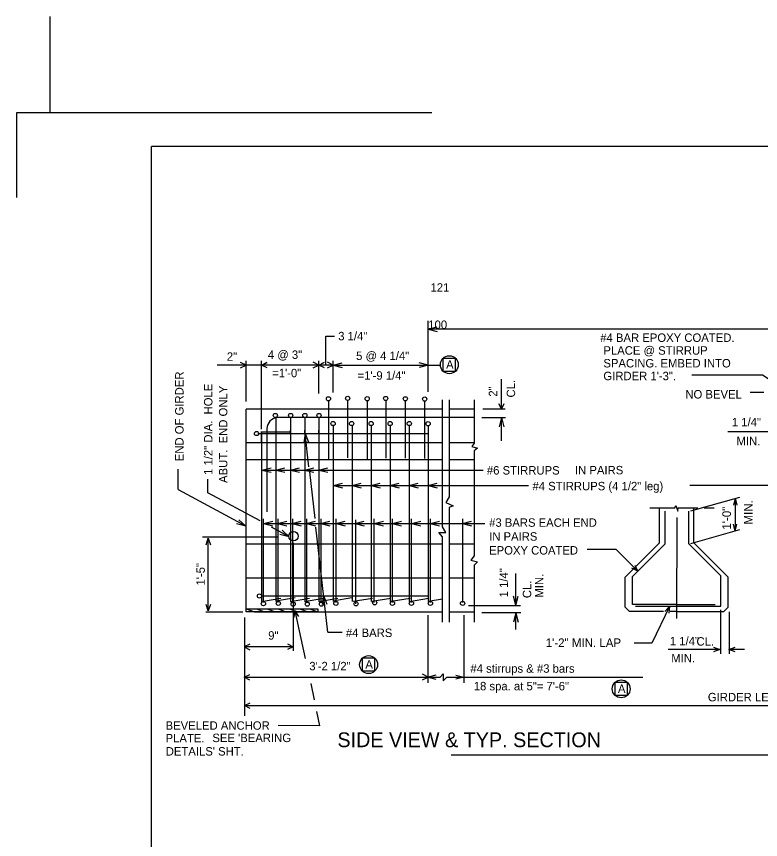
# Model space of a CAD drawing. Extents: x 1005.3 to 1101.9, y 1996.5 to 2073.3.
# Drawn here: x 1008.52 to 1037.89, y 2040.81 to 2073.29 of the extents above; entities that cross this region are included whole.
import ezdxf

# ---------------------------------------------------------------- set-up
doc = ezdxf.new("R2010")
doc.units = 0
for name, color, linetype in [('Level 1', 7, 'Continuous'), ('Level 2', 7, 'Continuous'), ('Level 5', 7, 'Continuous'), ('Level 6', 7, 'Continuous'), ('Level 60', 7, 'Continuous')]:
    doc.layers.add(name, color=color, linetype=linetype)

msp = doc.modelspace()

# ---------------------------------------------------------------- linework, layer by layer
at = {"layer": 'Level 1'}
for p, q in [((1024.919, 2069.489), (1008.518, 2069.489)), ((1008.518, 2069.489), (1008.518, 2066.149)), ((1013.852, 2012.158), (1013.852, 2068.156)), ((1097.517, 2068.156), (1013.852, 2068.156))]:
    msp.add_line(p, q, dxfattribs=at)
at = {"layer": 'Level 2'}
for p, q in [((1009.852, 2069.489), (1009.852, 2073.293)), ((1024.77, 2060.812), (1024.77, 2061.278)), ((1024.765, 2060.951), (1025.125, 2061.041)), ((1024.765, 2060.951), (1025.125, 2060.861)), ((1024.771, 2058.471), (1024.771, 2060.959)), ((1024.772, 2060.959), (1050.923, 2060.959)), ((1020.725, 2059.534), (1020.725, 2060.679)), ((1020.725, 2060.679), (1021.066, 2060.679)), ((1017.583, 2058.096), (1017.583, 2059.701)), ((1018.196, 2057.002), (1018.196, 2059.701)), ((1020.452, 2058.408), (1020.452, 2059.701)), ((1021.021, 2058.45), (1021.021, 2059.701)), ((1025.855, 2059.797), (1025.355, 2059.797)), ((1025.355, 2059.797), (1025.355, 2059.297)), ((1025.855, 2059.297), (1025.855, 2059.797)), ((1018.196, 2059.528), (1016.436, 2059.528)), ((1021.021, 2059.534), (1018.196, 2059.534)), ((1021.021, 2059.534), (1021.381, 2059.624)), ((1021.021, 2059.534), (1025.246, 2059.534)), ((1021.021, 2059.534), (1021.381, 2059.444)), ((1024.771, 2059.534), (1024.411, 2059.624)), ((1024.771, 2059.534), (1024.411, 2059.624)), ((1024.771, 2059.534), (1024.411, 2059.444)), ((1024.771, 2059.534), (1024.411, 2059.444)), ((1025.355, 2059.297), (1025.855, 2059.297)), ((1025.36, 2059.297), (1025.36, 2059.297)), ((1027.661, 2057.795), (1027.661, 2058.977)), ((1038.024, 2058.448), (1037.478, 2058.448)), ((1020.836, 2058.112), (1020.836, 2055.824)), ((1021.585, 2058.136), (1021.585, 2055.872)), ((1022.367, 2058.12), (1022.367, 2055.824)), ((1023.1, 2058.12), (1023.1, 2055.856)), ((1023.865, 2058.12), (1023.865, 2055.856)), ((1024.63, 2058.104), (1024.63, 2055.84)), ((1025.329, 2053.154), (1025.329, 2058.16)), ((1025.593, 2058.16), (1025.593, 2054.339)), ((1026.586, 2058.16), (1026.586, 2056.448)), ((1017.583, 2049.915), (1017.583, 2057.795)), ((1025.329, 2057.795), (1017.583, 2057.795)), ((1026.586, 2057.795), (1025.593, 2057.795)), ((1026.926, 2057.805), (1027.804, 2057.805)), ((1018.76, 2057.461), (1018.76, 2051.385)), ((1026.586, 2057.461), (1018.806, 2057.461)), ((1019.338, 2057.461), (1019.338, 2050.206)), ((1019.897, 2057.461), (1019.897, 2050.206)), ((1020.457, 2057.461), (1020.457, 2050.206)), ((1026.89, 2057.461), (1027.828, 2057.461)), ((1027.661, 2057.461), (1027.571, 2057.101)), ((1027.661, 2056.545), (1027.661, 2057.461)), ((1027.661, 2057.461), (1027.751, 2057.101)), ((1021.021, 2057.131), (1021.021, 2050.206)), ((1021.771, 2057.139), (1021.771, 2050.206)), ((1022.521, 2057.155), (1022.521, 2050.206)), ((1023.271, 2057.147), (1023.271, 2050.206)), ((1024.021, 2057.139), (1024.021, 2050.206)), ((1024.771, 2057.131), (1024.771, 2050.206)), ((1018.043, 2056.838), (1024.771, 2056.838)), ((1018.196, 2056.481), (1018.196, 2056.909)), ((1018.196, 2056.905), (1019.326, 2056.905)), ((1018.196, 2056.905), (1018.196, 2050.206)), ((1018.399, 2057.026), (1018.399, 2053.739)), ((1019.338, 2056.808), (1019.338, 2056.969)), ((1019.911, 2056.838), (1019.863, 2056.47)), ((1019.897, 2056.808), (1019.897, 2056.969)), ((1019.911, 2056.838), (1020.042, 2056.491)), ((1020.062, 2055.523), (1019.911, 2056.838)), ((1020.457, 2056.808), (1020.457, 2056.969)), ((1039.42, 2056.897), (1036.598, 2056.897)), ((1025.329, 2056.461), (1017.583, 2056.461)), ((1026.586, 2056.461), (1025.593, 2056.461)), ((1026.586, 2056.448), (1026.487, 2056.316)), ((1037.712, 2056.58), (1037.712, 2056.58)), ((1026.487, 2056.316), (1026.718, 2056.25)), ((1026.718, 2056.25), (1026.586, 2056.151)), ((1026.586, 2056.151), (1026.586, 2052.002)), ((1025.329, 2055.794), (1017.583, 2055.794)), ((1026.586, 2055.794), (1025.593, 2055.794)), ((1014.904, 2054.622), (1014.904, 2055.42)), ((1018.206, 2055.392), (1018.566, 2055.482)), ((1018.755, 2055.392), (1019.115, 2055.482)), ((1019.335, 2055.392), (1019.695, 2055.482)), ((1019.891, 2055.392), (1020.251, 2055.482)), ((1020.454, 2055.391), (1020.814, 2055.481)), ((1018.206, 2055.392), (1018.91, 2055.392)), ((1018.206, 2055.392), (1018.566, 2055.302)), ((1018.755, 2055.392), (1019.115, 2055.302)), ((1018.91, 2055.392), (1019.613, 2055.392)), ((1019.335, 2055.392), (1019.695, 2055.302)), ((1019.613, 2055.392), (1026.945, 2055.392)), ((1019.891, 2055.392), (1020.251, 2055.302)), ((1020.086, 2055.314), (1020.297, 2053.481)), ((1020.454, 2055.391), (1020.814, 2055.301)), ((1021.032, 2054.777), (1021.392, 2054.867)), ((1021.032, 2054.777), (1021.769, 2054.777)), ((1021.032, 2054.777), (1021.392, 2054.687)), ((1021.769, 2054.777), (1022.129, 2054.867)), ((1021.769, 2054.777), (1022.54, 2054.777)), ((1021.769, 2054.777), (1022.129, 2054.687)), ((1022.518, 2054.777), (1022.878, 2054.867)), ((1022.518, 2054.777), (1022.878, 2054.687)), ((1022.54, 2054.777), (1023.299, 2054.777)), ((1023.269, 2054.777), (1023.629, 2054.867)), ((1023.269, 2054.777), (1023.629, 2054.687)), ((1023.299, 2054.777), (1024.036, 2054.777)), ((1024.016, 2054.777), (1024.376, 2054.867)), ((1024.016, 2054.777), (1024.376, 2054.687)), ((1024.036, 2054.777), (1024.784, 2054.777)), ((1024.769, 2054.777), (1025.129, 2054.867)), ((1024.769, 2054.777), (1025.129, 2054.687)), ((1024.784, 2054.777), (1028.735, 2054.777)), ((1039.747, 2054.777), (1035.097, 2054.777)), ((1014.904, 2054.622), (1017.583, 2053.169)), ((1025.593, 2054.339), (1025.461, 2054.11)), ((1035.141, 2053.782), (1037.069, 2054.325)), ((1036.884, 2054.276), (1036.816, 2054.004)), ((1036.884, 2054.276), (1036.952, 2054.004)), ((1036.887, 2054.284), (1036.887, 2053)), ((1025.461, 2054.11), (1025.757, 2053.978)), ((1025.757, 2053.978), (1025.593, 2053.912)), ((1025.593, 2053.912), (1025.593, 2049.39)), ((1033.515, 2053.902), (1034.5, 2053.902)), ((1033.9, 2052.521), (1033.9, 2053.902)), ((1034.5, 2053.902), (1034.552, 2053.991)), ((1034.552, 2053.991), (1034.629, 2053.764)), ((1034.629, 2053.764), (1034.639, 2053.902)), ((1034.639, 2053.902), (1035.416, 2053.902)), ((1035.257, 2052.521), (1035.257, 2053.902)), ((1035.664, 2053.902), (1036.053, 2053.902)), ((1018.251, 2053.471), (1018.251, 2050.165)), ((1018.839, 2053.471), (1018.839, 2050.165)), ((1019.412, 2053.471), (1019.412, 2050.165)), ((1019.971, 2053.471), (1019.971, 2050.165)), ((1020.531, 2053.471), (1020.531, 2050.165)), ((1021.121, 2053.471), (1021.121, 2050.165)), ((1022.629, 2053.471), (1022.629, 2050.165)), ((1023.353, 2053.471), (1023.353, 2050.165)), ((1024.103, 2053.471), (1024.103, 2050.165)), ((1024.853, 2053.471), (1024.853, 2050.165)), ((1026.124, 2053.471), (1026.124, 2050.165)), ((1034.129, 2052.474), (1034.129, 2053.762)), ((1034.579, 2049.537), (1034.594, 2053.522)), ((1035.058, 2052.474), (1035.058, 2053.762)), ((1017.566, 2053.179), (1017.206, 2053.272)), ((1017.566, 2053.179), (1017.292, 2053.43)), ((1018.273, 2053.281), (1018.633, 2053.371)), ((1018.273, 2053.281), (1018.988, 2053.281)), ((1018.273, 2053.281), (1018.633, 2053.191)), ((1018.828, 2053.281), (1019.188, 2053.371)), ((1018.828, 2053.281), (1019.188, 2053.191)), ((1018.988, 2053.281), (1019.691, 2053.281)), ((1019.403, 2053.281), (1019.763, 2053.371)), ((1019.403, 2053.281), (1019.763, 2053.191)), ((1019.691, 2053.281), (1021.132, 2053.281)), ((1019.967, 2053.281), (1020.327, 2053.371)), ((1019.967, 2053.281), (1020.327, 2053.191)), ((1020.529, 2053.281), (1020.889, 2053.371)), ((1020.529, 2053.281), (1020.889, 2053.191)), ((1021.132, 2053.281), (1021.492, 2053.371)), ((1021.132, 2053.281), (1022.64, 2053.281)), ((1021.132, 2053.281), (1021.492, 2053.191)), ((1021.886, 2053.281), (1022.246, 2053.371)), ((1021.886, 2053.281), (1022.246, 2053.191)), ((1021.895, 2053.419), (1021.895, 2050.113)), ((1022.64, 2053.281), (1023, 2053.371)), ((1022.64, 2053.281), (1024.114, 2053.281)), ((1022.64, 2053.281), (1023, 2053.191)), ((1023.353, 2053.281), (1023.713, 2053.371)), ((1023.353, 2053.281), (1023.713, 2053.191)), ((1024.114, 2053.281), (1024.474, 2053.371)), ((1024.114, 2053.281), (1027.008, 2053.281)), ((1024.114, 2053.281), (1024.474, 2053.191)), ((1024.853, 2053.281), (1025.213, 2053.371)), ((1024.853, 2053.281), (1025.213, 2053.191)), ((1025.461, 2052.924), (1025.329, 2053.154)), ((1026.124, 2053.281), (1026.484, 2053.371)), ((1026.124, 2053.281), (1026.484, 2053.191)), ((1036.884, 2052.978), (1036.816, 2053.25)), ((1036.884, 2052.978), (1036.952, 2053.25)), ((1020.813, 2048.987), (1020.336, 2053.139)), ((1025.329, 2052.759), (1025.197, 2052.924)), ((1025.197, 2052.924), (1025.461, 2052.924)), ((1035.14, 2052.496), (1037.068, 2053.039)), ((1025.329, 2049.39), (1025.329, 2052.759)), ((1032.542, 2051.163), (1033.9, 2052.521)), ((1036.615, 2051.163), (1035.257, 2052.521)), ((1025.329, 2052.46), (1017.583, 2052.46)), ((1026.586, 2052.46), (1025.593, 2052.46)), ((1032.196, 2052.25), (1031.047, 2052.25)), ((1033.051, 2051.395), (1032.196, 2052.25)), ((1032.841, 2051.186), (1034.129, 2052.474)), ((1036.316, 2051.216), (1035.058, 2052.474)), ((1026.586, 2052.002), (1026.454, 2051.837)), ((1026.454, 2051.837), (1026.718, 2051.771)), ((1026.718, 2051.771), (1026.586, 2051.639)), ((1026.586, 2051.639), (1026.586, 2049.39)), ((1018.76, 2051.385), (1018.76, 2050.206)), ((1028.226, 2050.055), (1028.226, 2051.312)), ((1036.316, 2050.015), (1036.316, 2051.216)), ((1025.329, 2051.127), (1017.583, 2051.127)), ((1026.586, 2051.127), (1025.593, 2051.127)), ((1032.542, 2049.974), (1032.542, 2051.163)), ((1032.841, 2050.084), (1032.841, 2051.186)), ((1036.615, 2049.974), (1036.615, 2051.163)), ((1018.196, 2050.421), (1024.771, 2050.421)), ((1018.196, 2050.206), (1018.949, 2050.327)), ((1018.76, 2050.233), (1019.514, 2050.354)), ((1019.329, 2050.206), (1020.082, 2050.327)), ((1019.888, 2050.206), (1020.642, 2050.327)), ((1020.448, 2050.206), (1021.201, 2050.327)), ((1020.635, 2050.445), (1020.587, 2050.077)), ((1020.635, 2050.445), (1020.765, 2050.097)), ((1021.008, 2050.233), (1021.761, 2050.354)), ((1021.815, 2050.219), (1022.568, 2050.34)), ((1022.541, 2050.219), (1023.295, 2050.34)), ((1023.308, 2050.219), (1024.062, 2050.34)), ((1024.035, 2050.206), (1024.788, 2050.327)), ((1024.775, 2050.219), (1025.329, 2050.308)), ((1028.226, 2050.055), (1028.136, 2050.415)), ((1028.226, 2050.055), (1028.316, 2050.415)), ((1017.583, 2049.915), (1017.913, 2049.792)), ((1026.365, 2050.047), (1028.412, 2050.047)), ((1032.711, 2049.802), (1032.542, 2049.974)), ((1034.58, 2050.084), (1032.841, 2050.084)), ((1032.958, 2050.015), (1036.316, 2050.015)), ((1034.3, 2050.003), (1033.601, 2048.561)), ((1034.577, 2050.084), (1036.103, 2050.084)), ((1036.446, 2049.802), (1036.615, 2049.974)), ((1017.913, 2049.792), (1025.329, 2049.792)), ((1024.771, 2046.987), (1024.771, 2049.659)), ((1025.593, 2049.792), (1026.586, 2049.792)), ((1026.172, 2049.659), (1026.172, 2046.987)), ((1026.887, 2049.771), (1028.426, 2049.771)), ((1028.226, 2049.745), (1028.136, 2049.385)), ((1028.226, 2049.101), (1028.226, 2049.771)), ((1028.226, 2049.745), (1028.316, 2049.385)), ((1034.057, 2049.802), (1032.711, 2049.802)), ((1034.579, 2049.802), (1034.328, 2049.802)), ((1034.579, 2049.802), (1034.579, 2049.802)), ((1034.579, 2049.802), (1034.579, 2049.802)), ((1034.579, 2049.802), (1034.579, 2049.802)), ((1034.579, 2049.802), (1034.579, 2049.802)), ((1034.579, 2049.802), (1034.579, 2049.802)), ((1034.579, 2049.802), (1036.446, 2049.802)), ((1034.579, 2049.802), (1034.579, 2049.802)), ((1034.579, 2049.802), (1034.579, 2049.802)), ((1034.579, 2049.802), (1034.579, 2049.802)), ((1036.315, 2049.876), (1036.315, 2048.14)), ((1036.654, 2049.798), (1036.654, 2048.14)), ((1017.519, 2049.568), (1017.519, 2045.693)), ((1020.813, 2048.987), (1021.369, 2048.987)), ((1033.601, 2048.561), (1032.903, 2048.561)), ((1036.286, 2048.306), (1034.238, 2048.306)), ((1037.252, 2048.306), (1036.639, 2048.306)), ((1022.669, 2047.961), (1022.169, 2047.961)), ((1022.169, 2047.961), (1022.169, 2047.461)), ((1022.669, 2047.461), (1022.669, 2047.961)), ((1022.169, 2047.461), (1022.669, 2047.461)), ((1022.173, 2047.461), (1022.173, 2047.461)), ((1025.239, 2047.221), (1025.363, 2047.344)), ((1025.363, 2047.344), (1025.363, 2047.073)), ((1017.527, 2047.221), (1024.764, 2047.221)), ((1024.764, 2047.221), (1025.239, 2047.221)), ((1025.363, 2047.073), (1025.511, 2047.221)), ((1025.511, 2047.221), (1033.243, 2047.221)), ((1032.639, 2047.004), (1032.139, 2047.004)), ((1032.139, 2047.004), (1032.139, 2046.504)), ((1032.639, 2046.504), (1032.639, 2047.004)), ((1032.139, 2046.504), (1032.639, 2046.504)), ((1032.144, 2046.504), (1032.144, 2046.504)), ((1017.519, 2046.095), (1056.542, 2046.095)), ((1025.674, 2044.148), (1042.378, 2044.148))]:
    msp.add_line(p, q, dxfattribs=at)
for points in [[(1017.361, 2059.419), (1017.583, 2059.53), (1017.361, 2059.641)], [(1018.418, 2059.423), (1018.196, 2059.534), (1018.418, 2059.645)], [(1018.418, 2059.419), (1018.196, 2059.53), (1018.418, 2059.641)], [(1020.23, 2059.423), (1020.452, 2059.534), (1020.23, 2059.645)], [(1020.675, 2059.423), (1020.452, 2059.534), (1020.675, 2059.645)], [(1020.799, 2059.423), (1021.021, 2059.534), (1020.799, 2059.645)], [(1024.766, 2059.531), (1024.771, 2059.534), (1024.766, 2059.537)], [(1039.799, 2057.948), (1037.964, 2059.132), (1035.18, 2059.132)], [(1027.55, 2058.017), (1027.661, 2057.795), (1027.772, 2058.017)], [(1032.933, 2051.637), (1033.051, 2051.395), (1032.809, 2051.513)], [(1034.111, 2049.813), (1034.3, 2050.003), (1034.269, 2049.736)], [(1036.032, 2048.394), (1036.286, 2048.306), (1036.032, 2048.219)], [(1036.893, 2048.219), (1036.639, 2048.306), (1036.893, 2048.394)], [(1017.734, 2047.099), (1017.512, 2047.21), (1017.734, 2047.321)], [(1024.549, 2047.109), (1024.771, 2047.221), (1024.549, 2047.332)], [(1025.073, 2047.299), (1024.764, 2047.221), (1025.073, 2047.142)], [(1025.863, 2047.299), (1026.172, 2047.221), (1025.863, 2047.142)], [(1017.741, 2045.984), (1017.519, 2046.095), (1017.741, 2046.206)]]:
    msp.add_lwpolyline(points, dxfattribs=at)
for centre, radius in [((1025.605, 2059.547), 0.354), ((1020.834, 2058.202), 0.0833), ((1021.593, 2058.219), 0.0833), ((1022.364, 2058.205), 0.0833), ((1023.094, 2058.215), 0.0833), ((1023.867, 2058.203), 0.0833), ((1024.632, 2058.192), 0.0833), ((1018.735, 2057.545), 0.0833), ((1019.342, 2057.545), 0.0833), ((1019.902, 2057.545), 0.0833), ((1020.461, 2057.545), 0.0833), ((1021.017, 2057.226), 0.0833), ((1021.746, 2057.226), 0.0833), ((1022.519, 2057.226), 0.0833), ((1023.269, 2057.226), 0.0833), ((1024.024, 2057.226), 0.0833), ((1024.768, 2057.218), 0.0833), ((1017.994, 2056.832), 0.0833), ((1018.11, 2050.421), 0.0833), ((1022.656, 2050.153), 0.0833), ((1018.267, 2050.12), 0.0833), ((1018.855, 2050.131), 0.0833), ((1019.439, 2050.097), 0.0833), ((1019.998, 2050.097), 0.0833), ((1020.558, 2050.097), 0.0833), ((1021.126, 2050.131), 0.0833), ((1021.921, 2050.11), 0.0833), ((1023.358, 2050.131), 0.0833), ((1024.108, 2050.131), 0.0833), ((1024.858, 2050.131), 0.0833), ((1026.129, 2050.131), 0.0833), ((1022.419, 2047.711), 0.354), ((1032.389, 2046.754), 0.354)]:
    msp.add_circle(centre, radius, dxfattribs=at)
msp.add_arc((1018.865, 2056.998), 0.467, 96.657, 177.0425, dxfattribs=at)
at = {"layer": 'Level 5'}
for p, q in [((1016.076, 2054.497), (1016.076, 2055.029)), ((1018.136, 2053.381), (1016.076, 2054.497)), ((1019.28, 2052.76), (1018.587, 2053.136)), ((1019.28, 2052.76), (1018.921, 2052.852)), ((1019.28, 2052.76), (1019.007, 2053.011)), ((1018.819, 2052.744), (1015.861, 2052.744)), ((1016.09, 2049.832), (1016.09, 2052.699)), ((1019.437, 2052.522), (1019.437, 2048.253)), ((1017.454, 2049.787), (1015.998, 2049.787)), ((1019.437, 2048.419), (1017.527, 2048.419))]:
    msp.add_line(p, q, dxfattribs=at)
for points in [[(1016.002, 2052.445), (1016.09, 2052.699), (1016.177, 2052.445)], [(1016.177, 2050.086), (1016.09, 2049.832), (1016.002, 2050.086)], [(1017.734, 2048.52), (1017.512, 2048.409), (1017.734, 2048.298)], [(1019.215, 2048.531), (1019.437, 2048.419), (1019.215, 2048.308)]]:
    msp.add_lwpolyline(points, dxfattribs=at)
msp.add_circle((1019.455, 2052.778), 0.186, dxfattribs=at)
at = {"layer": 'Level 6'}
for p, q in [((1017.985, 2049.915), (1018.325, 2049.788)), ((1018.403, 2049.915), (1018.743, 2049.788)), ((1018.83, 2049.915), (1019.17, 2049.788)), ((1019.289, 2049.915), (1019.629, 2049.788)), ((1019.696, 2049.915), (1020.036, 2049.788)), ((1020.091, 2049.915), (1020.417, 2049.793)), ((1019.505, 2049.838), (1019.917, 2047.951)), ((1020.133, 2046.963), (1020.274, 2046.32)), ((1020.497, 2045.3), (1020.375, 2045.857)), ((1020.497, 2045.3), (1018.851, 2045.312))]:
    msp.add_line(p, q, dxfattribs=at)
msp.add_lwpolyline([(1017.583, 2049.915), (1020.417, 2049.915), (1020.417, 2049.788), (1017.583, 2049.788)], close=True, dxfattribs=at)
msp.add_lwpolyline([(1019.474, 2049.571), (1019.505, 2049.838), (1019.645, 2049.609)], dxfattribs=at)

# ---------------------------------------------------------------- texts
at = {"layer": 'Level 2'}
for s, height, p in [('3 1/4"', 0.3333, (1021.219, 2060.511)), ('#4 BAR EPOXY COATED. ', 0.33333, (1031.562, 2060.448)), (' PLACE @ STIRRUP', 0.33333, (1031.562, 2059.944)), ('2"', 0.3333, (1016.821, 2059.703)), ('4 @ 3" ', 0.3333, (1018.443, 2059.777)), ('5 @ 4 1/4"', 0.3333, (1021.925, 2059.733)), ('A', 0.333, (1025.477, 2059.387)), (' SPACING. EMBED INTO ', 0.33333, (1031.562, 2059.44)), ('=1\'-0"', 0.3333, (1018.612, 2059.052)), ('=1\'-9 1/4"', 0.3333, (1021.984, 2058.957)), (' GIRDER 1\'-3".', 0.33333, (1031.562, 2058.937)), ('NO BEVEL', 0.3333, (1034.922, 2058.214)), ('1 1/4"', 0.3333, (1036.758, 2057.114)), ('MIN.', 0.3333, (1036.942, 2056.368)), ('#6 STIRRUPS', 0.33333, (1027.087, 2055.213)), ('IN PAIRS', 0.3333, (1030.564, 2055.22)), ('#4 STIRRUPS (4 1/2" leg)', 0.33333, (1028.887, 2054.59)), ('#3 BARS EACH END', 0.33244, (1027.178, 2053.151)), ('IN PAIRS', 0.3324, (1027.178, 2052.603)), ('EPOXY COATED', 0.33244, (1027.178, 2052.055)), ('#4 BARS', 0.3333, (1021.522, 2048.801)), ('1\'-2" MIN. LAP', 0.34, (1029.41, 2048.404)), ('1 1/4"', 0.3333, (1034.31, 2048.474)), ('CL.', 0.3333, (1035.361, 2048.46)), ('MIN.', 0.3333, (1034.365, 2047.798)), ('3\'-2 1/2"', 0.3333, (1020.078, 2047.486)), ('A', 0.333, (1022.291, 2047.551)), ('#4 stirrups & #3 bars', 0.33333, (1026.437, 2047.39)), ('18 spa. at 5"= 7\'-6"', 0.33333, (1026.57, 2046.695)), ('A', 0.333, (1032.261, 2046.594)), ('GIRDER LENGTH =  "L"', 0.33333, (1035.81, 2046.261)), ('             SIDE VIEW & TYP. SECTION', 0.58333, (1018.37, 2044.452))]:
    msp.add_text(s, height=height, dxfattribs=at).set_placement(p)
for s, height, p in [('END OF GIRDER', 0.33333, (1015.115, 2055.738)), ('2"', 0.3333, (1027.495, 2058.286)), ('CL.', 0.3333, (1028.201, 2058.253)), ('MIN.', 0.34, (1037.573, 2053.241)), ('1\'-0"', 0.34, (1036.722, 2053.039)), ('1 1/4"', 0.3333, (1027.919, 2050.366)), ('MIN.', 0.3333, (1029.322, 2050.355)), ('CL.', 0.3333, (1028.837, 2050.334))]:
    msp.add_text(s, height=height, rotation=90, dxfattribs=at).set_placement(p)
at = {"layer": 'Level 5'}
for s, height, p in [('1 1/2" DIA.  HOLE', 0.33333, (1016.254, 2055.197)), ('ABUT.  END ONLY', 0.33333, (1016.844, 2054.881)), ('1\'-5"', 0.3333, (1015.953, 2050.833))]:
    msp.add_text(s, height=height, rotation=90, dxfattribs=at).set_placement(p)
msp.add_text('9"', height=0.3333, dxfattribs=at).set_placement((1018.455, 2048.695))
at = {"layer": 'Level 6'}
for s, height, p in [('BEVELED ANCHOR', 0.33333, (1014.405, 2045.14)), ('PLATE.', 0.3333, (1014.405, 2044.64)), ("SEE 'BEARING", 0.33333, (1016.251, 2044.653)), ("DETAILS' SHT.", 0.33333, (1014.411, 2044.121))]:
    msp.add_text(s, height=height, dxfattribs=at).set_placement(p)
at = {"layer": 'Level 60'}
for s, p in [('121', (1024.861, 2062.43)), ('100', (1024.774, 2060.96))]:
    msp.add_text(s, height=0.3333, dxfattribs=at).set_placement(p)

doc.saveas('drawing.dxf')
